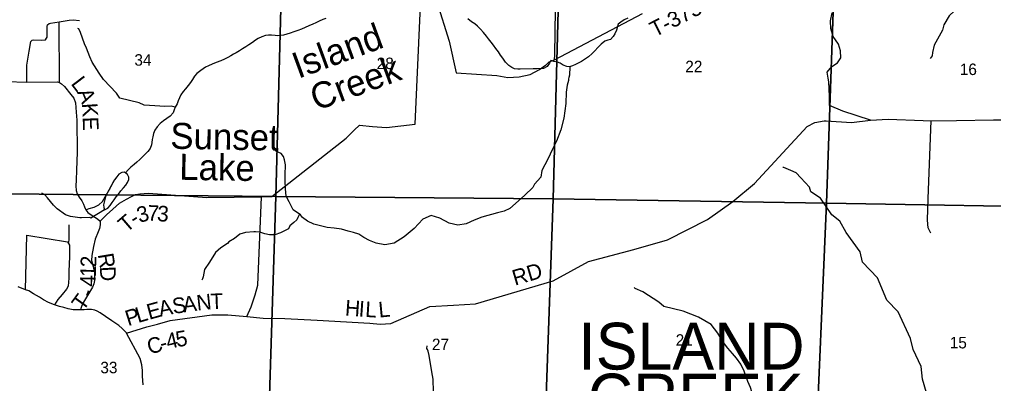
# Model space of a CAD drawing. Extents: x -19 to 40.8, y -1.8 to 26.1.
# Drawn here: x 4.462 to 8.007, y 18.273 to 19.6 of the extents above; entities that cross this region are included whole.
import ezdxf

# ---------------------------------------------------------------- set-up
doc = ezdxf.new("R2010")
doc.units = 0
for name, color, linetype in [('GM_X_Corporation', 7, 'Continuous'), ('GM_X_County_Road_Text', 7, 'Continuous'), ('GM_X_Minor_River', 7, 'Continuous'), ('GM_X_Minor_River_Text', 7, 'Continuous'), ('GM_X_Rail_Line', 7, 'Continuous'), ('GM_X_Section', 7, 'Continuous'), ('GM_X_Section_Text', 7, 'Continuous'), ('GM_X_State_Route', 7, 'Continuous'), ('GM_X_Township_Road_Text', 7, 'Continuous'), ('GM_X_Township_Text', 7, 'Continuous'), ('RW_P_Text', 7, 'Continuous'), ('SC_Shading1', 7, 'Continuous')]:
    doc.layers.add(name, color=color, linetype=linetype)

msp = doc.modelspace()

# ---------------------------------------------------------------- linework, layer by layer
at = {"layer": 'GM_X_Corporation'}
for points in [[(4.4143, 19.3744), (4.4882, 19.3722), (4.5995, 19.3727), (4.6072, 19.3708), (4.615, 19.3654), (4.6255, 19.3558), (4.6492, 19.3267), (4.6595, 19.3136), (4.6661, 19.2962), (4.668, 19.2629), (4.6701, 19.2337), (4.672, 19.1161), (4.6698, 19.0512), (4.6681, 19.0149), (4.6674, 18.9942), (4.6681, 18.9764), (4.6714, 18.9651), (4.6792, 18.9523), (4.6881, 18.9391), (4.6949, 18.9274), (4.6986, 18.9176), (4.7027, 18.9065), (4.7107, 18.8962), (4.7263, 18.8859), (4.7364, 18.88), (4.7459, 18.8741), (4.7555, 18.8652), (4.7554, 18.8516), (4.7529, 18.839), (4.7479, 18.8263), (4.7373, 18.799), (4.7307, 18.7734), (4.7246, 18.7398), (4.7241, 18.7221), (4.73, 18.6994), (4.7351, 18.6765), (4.7342, 18.6492), (4.732, 18.6374), (4.7274, 18.6247), (4.7053, 18.588), (4.6912, 18.5634), (4.6858, 18.5502), (4.6836, 18.5417)], [(6.0409, 18.5594), (6.122, 18.5643), (6.4042, 18.6479), (6.5329, 18.7179), (6.6978, 18.7619), (6.8204, 18.797), (6.9658, 18.8707), (7.0584, 18.9371), (7.1364, 19.0024), (7.3281, 19.2106), (7.3559, 19.225), (7.39, 19.2307), (7.398, 19.2302)], [(7.398, 19.2302), (7.4905, 19.225), (7.5586, 19.2329), (7.6231, 19.2366), (7.7512, 19.2321)], [(7.7512, 19.2321), (7.7801, 19.2311), (7.8722, 19.2319), (8.0068, 19.2346), (8.0647, 19.2339), (8.1097, 19.2329), (8.145, 19.2283)], [(4.8515, 18.457), (4.9248, 18.4803), (4.9642, 18.49), (5.01, 18.5032), (5.1622, 18.5237), (5.2196, 18.5237), (5.2892, 18.5175), (5.3482, 18.5122), (5.4273, 18.51), (5.5447, 18.5041), (5.7364, 18.4932), (5.775, 18.4899), (5.8128, 18.4918), (5.9549, 18.5542), (6.0409, 18.5594)]]:
    msp.add_lwpolyline(points, dxfattribs=at)
at = {"layer": 'GM_X_Rail_Line'}
for points in [[(4.8509, 18.4578), (4.8357, 18.4742), (4.8235, 18.485), (4.7979, 18.5014), (4.7746, 18.5172), (4.7558, 18.5313), (4.7447, 18.5377), (4.736, 18.5413), (4.7238, 18.5433), (4.7073, 18.5437), (4.6968, 18.5426), (4.6836, 18.5417), (4.6574, 18.5418), (4.639, 18.5454), (4.6228, 18.5503), (4.6074, 18.5548), (4.5886, 18.5603), (4.5672, 18.5683), (4.5489, 18.5787), (4.5343, 18.5881), (4.5132, 18.6009), (4.4956, 18.6107), (4.4834, 18.6148), (4.4574, 18.6255)], [(4.9116, 18.2692), (4.9099, 18.3009), (4.9093, 18.3208), (4.9073, 18.3415), (4.9008, 18.3643), (4.8515, 18.457), (4.8509, 18.4578)]]:
    msp.add_lwpolyline(points, dxfattribs=at)
at = {"layer": 'GM_X_Section'}
for points in [[(8.026, 19.7527), (7.9933, 19.74), (7.9586, 19.712), (7.9148, 19.6892), (7.9056, 19.6723), (7.8454, 19.6135), (7.8263, 19.5812), (7.821, 19.5613), (7.7909, 19.5064), (7.7846, 19.4804), (7.7829, 19.4675), (7.7767, 19.4575)], [(6.6753, 19.6047), (6.6626, 19.5986), (6.6503, 19.5906), (6.6406, 19.5831), (6.6341, 19.5612), (6.628, 19.5484), (6.6223, 19.538), (6.6123, 19.527), (6.6025, 19.5248), (6.5916, 19.521), (6.579, 19.5104), (6.5679, 19.4993), (6.5551, 19.4849), (6.5455, 19.4762), (6.5325, 19.4643), (6.5184, 19.454), (6.5072, 19.4476), (6.4971, 19.4423), (6.4851, 19.4358), (6.4742, 19.4313), (6.4633, 19.4271), (6.4534, 19.4287), (6.4411, 19.4341), (6.4298, 19.4406)], [(5.5773, 19.6041), (5.5653, 19.5999), (5.5522, 19.5945), (5.5406, 19.5885), (5.5293, 19.5832), (5.5154, 19.5766), (5.5012, 19.5708), (5.488, 19.5651), (5.4745, 19.5597), (5.4606, 19.5547), (5.4471, 19.5501), (5.4346, 19.5463), (5.4222, 19.5432), (5.412, 19.5418), (5.4021, 19.5411), (5.3918, 19.5419), (5.3789, 19.5426), (5.3682, 19.5427), (5.3568, 19.5415), (5.3437, 19.5373), (5.3309, 19.5308), (5.3209, 19.5248), (5.3093, 19.5168), (5.2967, 19.5077), (5.2859, 19.5001), (5.2735, 19.4928), (5.262, 19.4856), (5.2508, 19.4792), (5.2407, 19.4739), (5.2306, 19.4679)], [(6.4298, 19.4406), (6.4202, 19.4441), (6.406, 19.4474), (6.3953, 19.4505), (6.3903, 19.4405), (6.3819, 19.4288), (6.3692, 19.4211), (6.346, 19.4204), (6.3312, 19.4207), (6.2845, 19.4192), (6.275, 19.4193), (6.2639, 19.4205), (6.2539, 19.4251), (6.2423, 19.4324), (6.2301, 19.4445), (6.2205, 19.4591), (6.2126, 19.4699), (6.2046, 19.4818), (6.1959, 19.4941), (6.1868, 19.5064), (6.178, 19.5179), (6.1689, 19.5294), (6.161, 19.5395), (6.1504, 19.5524), (6.1393, 19.5654), (6.1291, 19.5754), (6.1194, 19.5842), (6.1073, 19.5915), (6.0937, 19.6024)], [(5.0288, 19.2804), (5.0132, 19.284), (4.9913, 19.2832), (4.9546, 19.2853), (4.9153, 19.2884), (4.8974, 19.2961), (4.8264, 19.3128), (4.8147, 19.3317), (4.7674, 19.3819), (4.7515, 19.4045), (4.7262, 19.4451), (4.7172, 19.4644), (4.7057, 19.4954), (4.6986, 19.5109), (4.6835, 19.5529), (4.678, 19.5658), (4.6746, 19.5672)], [(5.2306, 19.4679), (5.2205, 19.4622), (5.2074, 19.4557), (5.1943, 19.45), (5.1781, 19.443), (5.1627, 19.4368), (5.1496, 19.4307), (5.1387, 19.4258), (5.1212, 19.4142), (5.1075, 19.4031), (5.0987, 19.3933), (5.0911, 19.3809), (5.0838, 19.3704), (5.0754, 19.3594), (5.0658, 19.3477), (5.0574, 19.3375), (5.0487, 19.3251), (5.0437, 19.315), (5.0395, 19.3035), (5.0356, 19.2931), (5.0288, 19.2803), (5.0253, 19.2707), (5.0207, 19.2595), (5.0107, 19.2481), (4.9981, 19.239), (4.9854, 19.2306), (4.9739, 19.2207), (4.9625, 19.2093), (4.9542, 19.1969), (4.9492, 19.1849), (4.9469, 19.173), (4.9449, 19.1627), (4.9437, 19.1524), (4.9418, 19.1428), (4.9376, 19.1305), (4.9292, 19.1188), (4.9196, 19.1098), (4.9092, 19.0999), (4.8996, 19.0905), (4.8893, 19.0806), (4.8789, 19.0716), (4.8675, 19.0621), (4.8571, 19.0526), (4.8477, 19.0408)], [(6.465, 19.4278), (6.4633, 19.3977), (6.4612, 19.3885), (6.4601, 19.3843), (6.4599, 19.3782), (6.4545, 19.361), (6.4512, 19.3354), (6.4496, 19.2943), (6.4433, 19.2402), (6.4316, 19.1981), (6.4164, 19.1568), (6.4011, 19.1273), (6.3847, 19.0916), (6.3627, 19.0494), (6.359, 19.0257), (6.3356, 19.0006), (6.3302, 18.988), (6.3004, 18.9597), (6.2777, 18.9396), (6.2461, 18.9109), (6.2262, 18.9022), (6.2021, 18.8961), (6.1442, 18.8803), (6.116, 18.8684), (6.0875, 18.8558), (6.0573, 18.8511), (6.0251, 18.8581), (5.9922, 18.8766), (5.9603, 18.8863), (5.9303, 18.8725), (5.898, 18.8385), (5.8623, 18.8075), (5.8256, 18.7856), (5.791, 18.7789), (5.7602, 18.7852), (5.7359, 18.7947), (5.7156, 18.8062), (5.6969, 18.8173), (5.6779, 18.8242), (5.6574, 18.8288), (5.6334, 18.836), (5.6073, 18.8397), (5.5815, 18.8427), (5.5569, 18.8476), (5.5333, 18.8548), (5.5104, 18.8655), (5.4917, 18.8789), (5.4851, 18.8883), (5.4579, 18.9068), (5.4438, 18.9351), (5.4329, 18.9566), (5.4294, 18.9824), (5.4289, 19.0124), (5.4289, 19.0341), (5.4294, 19.071), (5.4257, 19.0885), (5.4232, 19.1014), (5.4147, 19.1123), (5.4051, 19.1159), (5.3945, 19.1207)], [(7.7628, 18.2398), (7.748, 18.289), (7.743, 18.3353), (7.7147, 18.398), (7.7049, 18.4373), (7.6593, 18.5351), (7.6189, 18.5774), (7.5846, 18.6582), (7.5303, 18.7162), (7.5209, 18.7534), (7.4709, 18.8233), (7.4471, 18.8647), (7.4187, 18.8886), (7.3773, 18.9484), (7.3424, 18.9721), (7.3365, 18.9888), (7.3049, 19.0236), (7.2891, 19.0412), (7.2693, 19.0497), (7.2437, 19.0607), (7.2403, 19.0606)], [(4.7715, 18.9068), (4.7209, 18.8762), (4.7179, 18.8781), (4.6877, 18.8772), (4.6816, 18.8771), (4.6471, 18.8819), (4.6292, 18.8888), (4.5986, 18.91), (4.5852, 18.923), (4.5632, 18.9501), (4.5539, 18.9613), (4.5428, 18.9676)], [(5.4813, 18.8909), (5.4751, 18.8786), (5.4707, 18.8701), (5.4599, 18.8608), (5.4454, 18.848), (5.441, 18.8369), (5.4118, 18.8224), (5.3915, 18.8152), (5.3722, 18.8152), (5.3547, 18.8195), (5.3369, 18.8253), (5.3206, 18.8266), (5.3149, 18.8265), (5.284, 18.8237), (5.2637, 18.8176), (5.2439, 18.8021), (5.2233, 18.7903), (5.2193, 18.7834), (5.195, 18.7686), (5.1749, 18.7515), (5.1536, 18.7154), (5.1351, 18.6892), (5.1299, 18.6625), (5.1282, 18.6545), (5.1256, 18.6507)], [(7.1409, 18.1563), (7.1357, 18.1752), (7.1356, 18.1801), (7.1347, 18.185), (7.1286, 18.215), (7.1269, 18.2431), (7.1225, 18.2593), (7.1123, 18.2812), (7.0988, 18.3183), (7.0877, 18.3439), (7.0715, 18.3657), (7.0568, 18.3826), (7.0402, 18.4021), (7.0239, 18.4231), (7.0033, 18.4573), (6.9789, 18.4881), (6.9335, 18.5155), (6.8768, 18.5366), (6.8073, 18.5541), (6.7892, 18.5694), (6.7304, 18.6079), (6.7022, 18.6204), (6.6987, 18.623)], [(6.0242, 17.98), (6.0157, 17.998), (6.0089, 18.0195), (6.0068, 18.0533), (5.9994, 18.084), (5.9853, 18.1788), (5.969, 18.2435), (5.967, 18.2899), (5.9628, 18.3157), (5.9531, 18.3752), (5.9494, 18.3915), (5.9466, 18.3975), (5.9447, 18.4016), (5.946, 18.4104)]]:
    msp.add_lwpolyline(points, dxfattribs=at)
at = {"layer": 'GM_X_State_Route'}
msp.add_line((6.4085, 19.4527), (6.4096, 19.4709), dxfattribs=at)
for points in [[(4.7555, 18.8652), (4.7783, 18.888), (4.8009, 18.9087), (4.8259, 18.9303), (4.8512, 18.9451), (4.869, 18.9552), (4.8845, 18.962), (4.8996, 18.9646), (4.9313, 18.9667), (5.1433, 18.9509), (5.3426, 18.9544), (5.3804, 18.955), (5.6506, 19.168), (5.6799, 19.1967), (5.6992, 19.215), (5.7466, 19.2107), (5.7973, 19.2071), (5.9023, 19.2192), (5.921, 19.6494)], [(5.9805, 19.6643), (6.0254, 19.5216), (6.0512, 19.4062), (6.1994, 19.3959), (6.2389, 19.3884), (6.28, 19.3915), (6.3199, 19.3999), (6.354, 19.4181), (6.3766, 19.4338), (6.3782, 19.435), (6.3805, 19.4372)], [(6.3805, 19.4372), (6.3897, 19.4462), (6.4085, 19.4527), (6.7287, 19.622)], [(6.4096, 19.4709), (6.4097, 19.4727), (6.412, 19.6359)], [(7.4054, 19.3862), (7.4019, 19.4087), (7.4189, 19.4286), (7.4395, 19.4422), (7.4507, 19.4604), (7.4502, 19.486), (7.4421, 19.5101), (7.4235, 19.5384), (7.4149, 19.5672), (7.4133, 19.5955), (7.419, 19.6246)], [(4.4882, 19.3722), (4.4881, 19.4337), (4.4972, 19.4848), (4.5036, 19.5195), (4.508, 19.5242), (4.5139, 19.5257), (4.5423, 19.5248), (4.5566, 19.5261), (4.5602, 19.5316), (4.5621, 19.5352), (4.5628, 19.5392), (4.563, 19.5551), (4.562, 19.5702), (4.5622, 19.5754), (4.5638, 19.5802), (4.5694, 19.5849), (4.5749, 19.5871), (4.6067, 19.5911)], [(4.6072, 19.3708), (4.6067, 19.5911), (4.6427, 19.5982), (4.6568, 19.5989), (4.6801, 19.5959)], [(7.5586, 19.2329), (7.458, 19.2658), (7.4096, 19.2869), (7.4096, 19.321), (7.4075, 19.3725), (7.4054, 19.3862)], [(7.7788, 18.8215), (7.7691, 18.8403), (7.7659, 18.8688), (7.7684, 18.9473), (7.7801, 19.2311)], [(4.7027, 18.9065), (4.7148, 18.9109), (4.7337, 18.916), (4.7505, 18.9245), (4.7635, 18.9365), (4.7915, 18.9858), (4.8056, 19.0117)], [(5.2892, 18.5175), (5.3049, 18.5529), (5.3198, 18.5965), (5.3297, 18.6323), (5.3426, 18.9544)], [(4.6403, 18.7833), (4.6419, 18.7882), (4.6423, 18.7979), (4.6426, 18.852)], [(4.4834, 18.6148), (4.4883, 18.8142), (4.6361, 18.7903), (4.6433, 18.7782), (4.6433, 18.7347), (4.6415, 18.6826), (4.6415, 18.6579), (4.6388, 18.6281), (4.6326, 18.6178), (4.617, 18.5979), (4.6012, 18.5794), (4.5886, 18.5603)]]:
    msp.add_lwpolyline(points, dxfattribs=at)
at = {"layer": 'RW_P_Text'}
for points in [[(4.4266, 19.9772), (5.4217, 19.9611), (5.3949, 18.9546), (4.411, 18.9653), (4.4251, 19.8945)], [(5.4217, 19.9611), (6.4302, 19.9522), (6.4041, 18.9461), (5.3949, 18.9546)], [(6.4302, 19.9522), (7.4345, 19.9428), (7.3987, 18.9308), (6.4041, 18.9461)], [(7.4345, 19.9428), (8.4338, 19.9356), (8.4001, 18.9137), (7.3987, 18.9308)], [(5.3949, 18.9546), (6.4041, 18.9461), (6.3691, 17.9545), (5.3629, 17.962)], [(6.4041, 18.9461), (7.3987, 18.9308), (7.3559, 17.9489), (6.3691, 17.9545)], [(7.3987, 18.9308), (8.4001, 18.9137), (8.3666, 17.9389), (7.3559, 17.9489)]]:
    msp.add_lwpolyline(points, close=True, dxfattribs=at)
msp.add_lwpolyline([(4.9335, 17.9644), (4.397, 17.9674), (4.4081, 18.8788), (4.411, 18.9653), (5.3949, 18.9546), (5.3629, 17.962), (5.0299, 17.9638)], dxfattribs=at)
at = {"layer": 'SC_Shading1'}
for points in [[(4.7715, 18.9068), (4.7828, 18.9121), (4.7916, 18.9223), (4.7988, 18.9328), (4.8058, 18.9425), (4.8142, 18.9535), (4.8222, 18.9636), (4.831, 18.9753), (4.8398, 18.9862), (4.8482, 18.9968), (4.8543, 19.0065), (4.8594, 19.0165), (4.8594, 19.026), (4.8553, 19.0358), (4.8437, 19.0434), (4.8338, 19.0424), (4.8234, 19.0359), (4.8157, 19.0262), (4.8081, 19.0157), (4.8012, 19.0048), (4.7954, 18.994), (4.7933, 18.9901)], [(4.7933, 18.9901), (4.79, 18.9843), (4.785, 18.9742), (4.78, 18.9646), (4.7754, 18.9541), (4.7719, 18.9441), (4.7695, 18.9345), (4.7675, 18.925), (4.7682, 18.9147), (4.7715, 18.9068)]]:
    msp.add_lwpolyline(points, dxfattribs=at)

# ---------------------------------------------------------------- texts
at = {"layer": 'GM_X_County_Road_Text'}
for s, height, rotation, p in [('L', 0.0568, 307.3773, (4.6467, 19.3659)), ('A', 0.0568, 292.2195, (4.6705, 19.3356)), ('K', 0.0568, 274.0067, (4.6884, 19.294)), ('E', 0.0568, 271.7188, (4.6918, 19.2447)), ('R', 0.0568, 279.4963, (4.7465, 18.7439)), ('D', 0.0568, 273.2073, (4.754, 18.6995)), ('RD', 0.05682, 16.4177, (6.2648, 18.6298)), ('A', 0.0568, 12.1108, (4.9738, 18.5166)), ('S', 0.0568, 8.2148, (5.0217, 18.527)), ('A', 0.0568, 7.5036, (5.0595, 18.5324)), ('N', 0.0568, 6.0948, (5.1087, 18.5389)), ('T', 0.0568, 2.1519, (5.1574, 18.5441)), ('H', 0.0568, 356.019, (5.6452, 18.5215)), ('P', 0.0568, 17.4101, (4.8569, 18.4822)), ('L', 0.0568, 16.5712, (4.8932, 18.4936)), ('E', 0.0568, 15.3014, (4.9337, 18.5056)), ('I', 0.0568, 356.0226, (5.695, 18.518)), ('L', 0.0568, 356.2885, (5.7186, 18.5164)), ('L', 0.0568, 5.4297, (5.7707, 18.5138)), ('C', 0.0568, 16.2462, (4.9355, 18.3786)), ('4', 0.0568, 13.852, (5.0022, 18.3978)), ('5', 0.0568, 9.4409, (5.035, 18.4059)), ('-', 0.0568, 15.6248, (4.9801, 18.3916))]:
    msp.add_text(s, height=height, rotation=rotation, dxfattribs=at).set_placement(p)
at = {"layer": 'GM_X_Minor_River'}
for s, rotation, p in [('Island', 20.13, (5.4761, 19.3837)), ('Creek', 20.1286, (5.5415, 19.2663))]:
    msp.add_text(s, height=0.09474, rotation=rotation, dxfattribs=at).set_placement(p)
at = {"layer": 'GM_X_Minor_River_Text'}
for s, rotation, p in [('Sunset', 358.9676, (5.0102, 19.1293)), ('Lake', 358.9681, (5.0426, 19.0162))]:
    msp.add_text(s, height=0.09471, rotation=rotation, dxfattribs=at).set_placement(p)
at = {"layer": 'GM_X_Section_Text'}
for s, p in [('34', (4.8799, 19.4318)), ('28', (5.7619, 19.4193)), ('22', (6.8849, 19.4079)), ('16', (7.884, 19.3976)), ('27', (5.9628, 18.3951)), ('21', (6.8499, 18.4112)), ('15', (7.8474, 18.4015)), ('33', (4.7561, 18.3109))]:
    msp.add_text(s, height=0.04186, rotation=0, dxfattribs=at).set_placement(p)
at = {"layer": 'GM_X_Township_Road_Text'}
for s, height, rotation, p in [('T-373', 0.05682, 26.9405, (6.7743, 19.5347)), ('3', 0.0568, 15.6709, (4.8976, 18.8584)), ('7', 0.0568, 357.1418, (4.9265, 18.8673)), ('3', 0.0568, 355.9845, (4.9611, 18.8656)), ('T', 0.0568, 40.6473, (4.8514, 18.8212)), ('-', 0.0568, 32.7807, (4.882, 18.8476)), ('2', 0.0568, 88.5622, (4.7406, 18.6963)), ('1', 0.0568, 88.194, (4.7395, 18.6609)), ('4', 0.0568, 88.6761, (4.7387, 18.626)), ('-', 0.0568, 68.8952, (4.7262, 18.5834)), ('T', 0.0568, 53.9213, (4.6934, 18.5349))]:
    msp.add_text(s, height=height, rotation=rotation, dxfattribs=at).set_placement(p)
at = {"layer": 'GM_X_Township_Text'}
for s, p in [('ISLAND', (6.4957, 18.3245)), ('CREEK', (6.5302, 18.139))]:
    msp.add_text(s, height=0.17045, rotation=0, dxfattribs=at).set_placement(p)

doc.saveas('drawing.dxf')
